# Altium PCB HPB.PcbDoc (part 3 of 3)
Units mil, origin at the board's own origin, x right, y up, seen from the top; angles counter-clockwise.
Board outline 7000 x 12000 mil, 6 copper layers (Top Layer, Int1 (GND), Int2 (Sign), Int3 (Sign), Int4 (PWR), Bottom Layer), stack 61.068 mil thick; 321 components, 232 nets, 1034 pads, 269 vias.
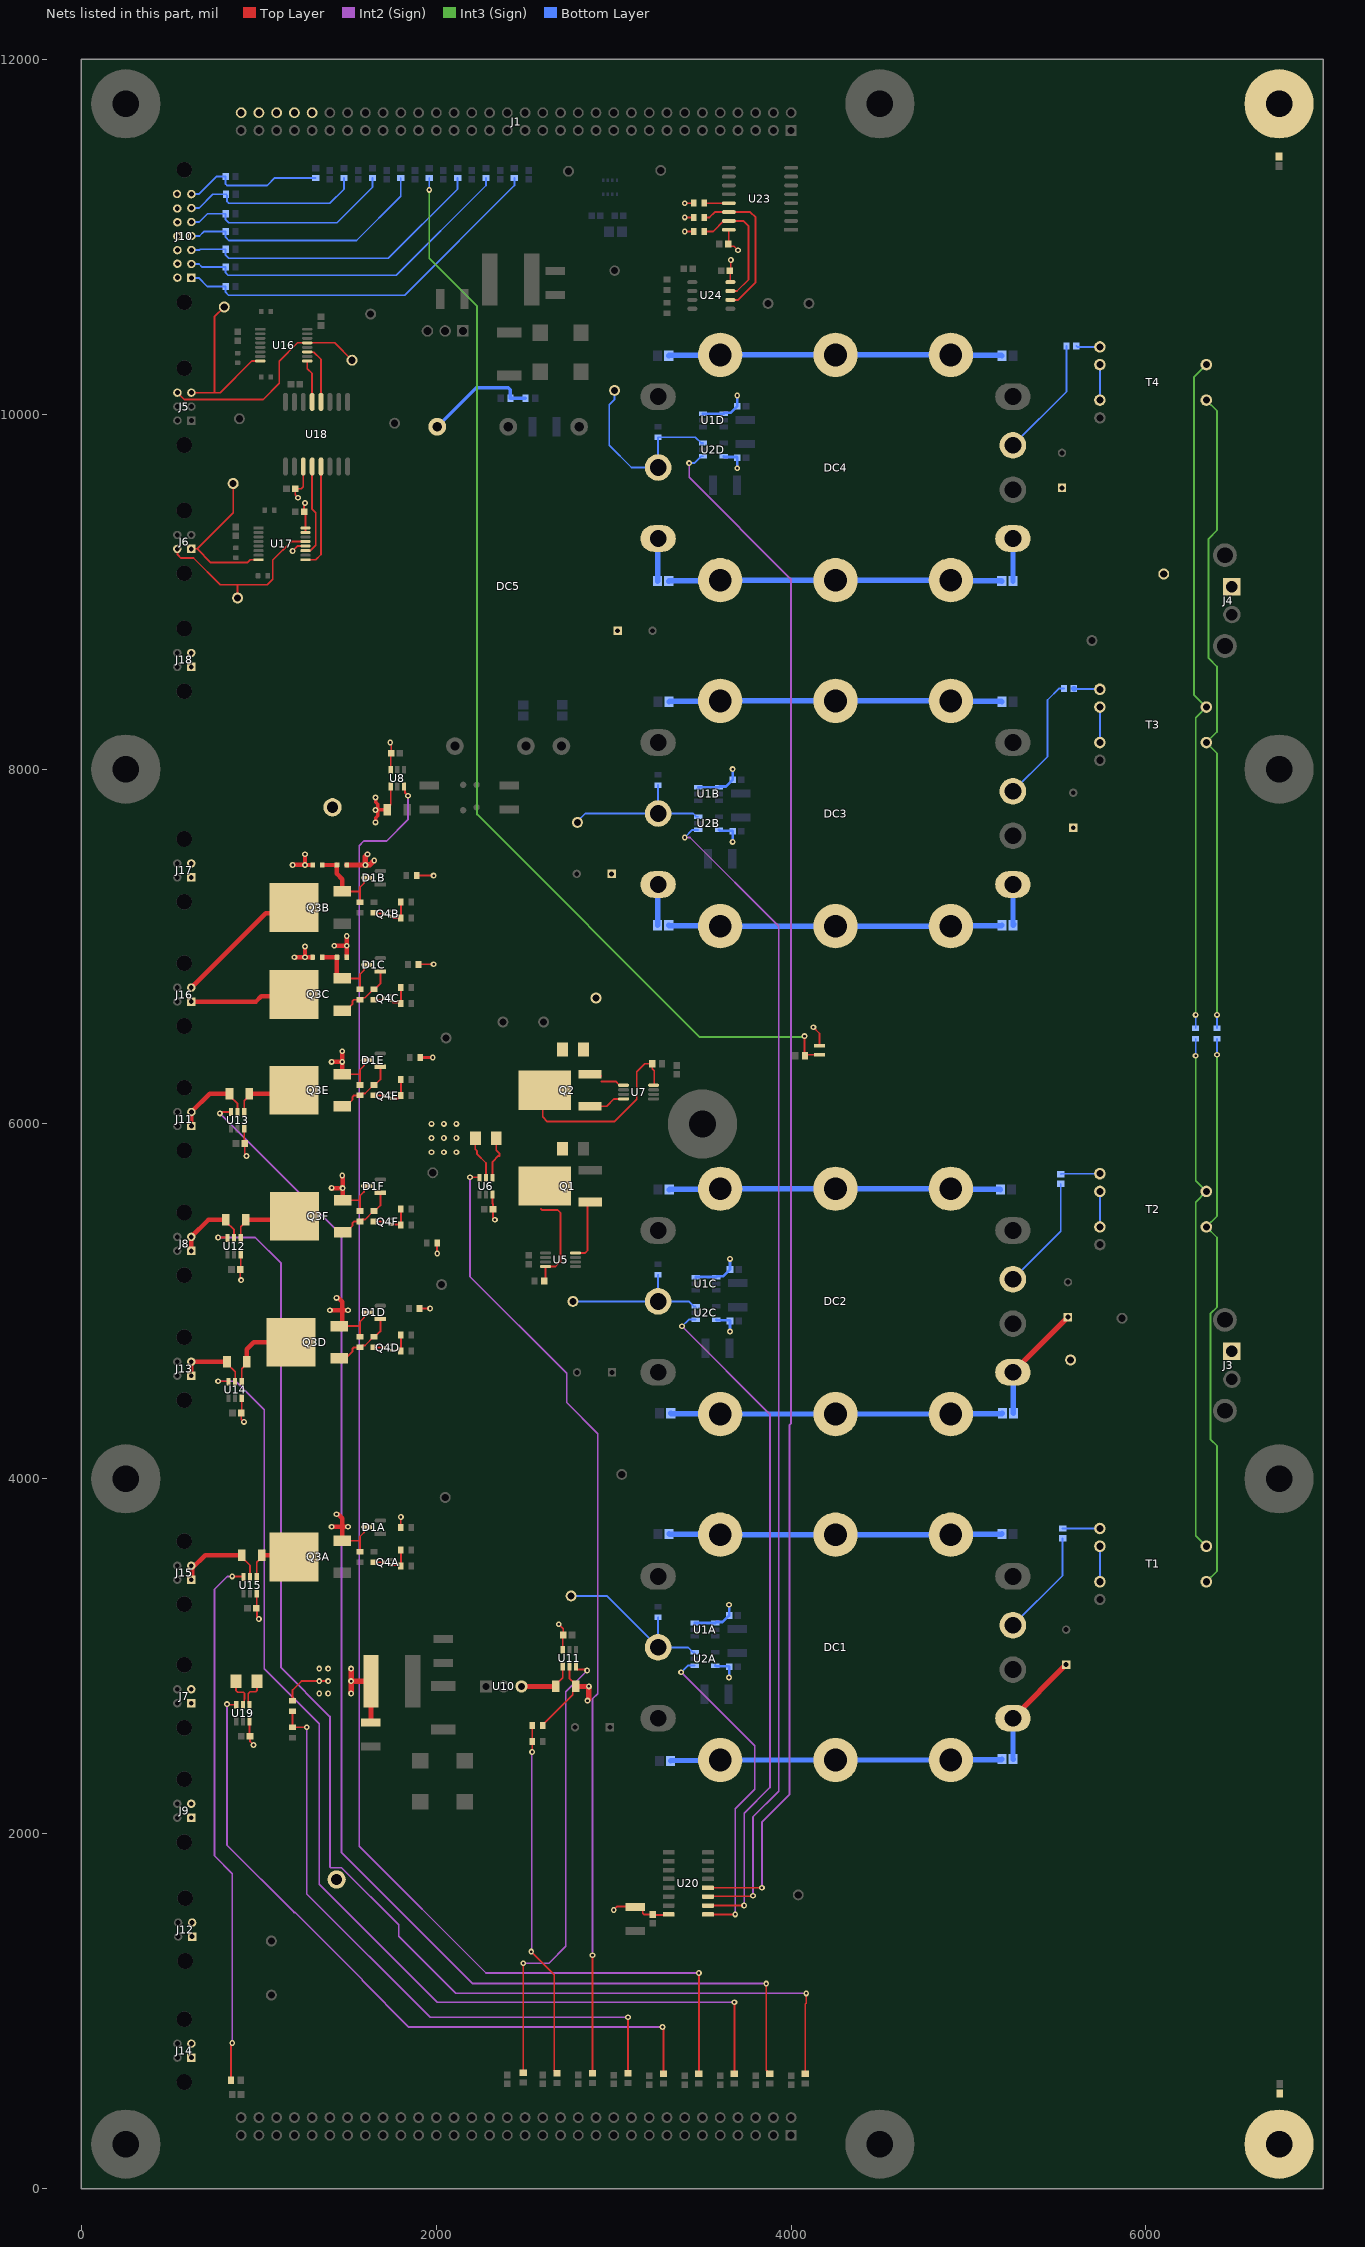
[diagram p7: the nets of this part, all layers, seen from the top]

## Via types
v1: diameter 33, hole 15, Top Layer to Bottom Layer, 269 vias

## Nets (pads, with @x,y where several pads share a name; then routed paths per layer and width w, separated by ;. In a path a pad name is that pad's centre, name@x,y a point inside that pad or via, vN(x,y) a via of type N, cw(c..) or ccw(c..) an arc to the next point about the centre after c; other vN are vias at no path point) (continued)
NetD1B_3: D1B.3 Q3B.3 R47.1 R48.1 R69B.1 | length 504.4
  Top Layer w10: Q3B.3@1470.12,7311.02 1568.22,7311.02 1570,7312.8 ; R69B.1@1570,7250 1570,7312.8 ; D1B.3@1608.19,7388.07 1598.8,7388.07 1592.47,7381.73 1592.47,7357.94 1570,7335.47 1570,7312.8
  Top Layer w25: R47.1@1357.56,7460 R48.1@1440,7460 1440,7410 1470.12,7379.88 Q3B.3@1470.12,7310.55
NetD1C_1: D1C.1 Q3C.1 R69C.2 R78C.2 | length 336.5
  Top Layer w10: Q3C.1@1489.8,6639.45 1528.24,6677.89 1528.24,6693.4 1535.31,6700.47 R69C.2@1570,6700.47 1580.75,6711.22 1597.76,6711.22 1646.06,6759.53 R78C.2@1650,6759.53 1653.94,6759.53 1685,6790.59 D1C.1@1685,6860.2
NetD1C_3: D1C.3 Q3C.3 R43.1 R44.1 R69C.1 | length 482
  Top Layer w10: Q3C.3@1470.12,6820.55 1568.22,6820.55 1570,6822.33 ; R69C.1@1570,6759.53 1570,6822.33 ; D1C.3@1608.19,6897.6 1598.8,6897.6 1592.47,6891.26 1592.47,6867.47 1570,6845 1570,6822.33
  Top Layer w25: R43.1@1357.56,6940 R44.1@1440,6940 1440,6837.58 1457.03,6820.55 Q3C.3@1470.12,6820.55
NetD1D_1: D1D.1 Q3D.1 R69D.2 R78D.2 | length 336.5
  Top Layer w10: Q3D.1@1489.8,4679.92 1528.24,4718.36 1528.24,4733.87 1535.31,4740.94 R69D.2@1570,4740.94 1580.75,4751.69 1597.76,4751.69 1646.06,4800 R78D.2@1650,4800 1653.94,4800 1685,4831.06 D1D.1@1685,4900.67
NetD1E_1: D1E.1 Q3E.1 R69E.2 R78E.2 | length 336.5
  Top Layer w10: Q3E.1@1489.8,6099.92 1528.24,6138.36 1528.24,6153.87 1535.31,6160.94 R69E.2@1570,6160.94 1580.75,6171.69 1597.76,6171.69 1646.06,6220 R78E.2@1650,6220 1653.94,6220 1685,6251.06 D1E.1@1685,6320.67
NetD1F_1: D1F.1 Q3F.1 R69F.2 R78F.2 | length 336.5
  Top Layer w10: Q3F.1@1489.8,5389.45 1528.24,5427.89 1528.24,5443.4 1535.31,5450.47 R69F.2@1570,5450.47 1580.75,5461.22 1597.76,5461.22 1646.06,5509.53 R78F.2@1650,5509.53 1653.94,5509.53 1685,5540.59 D1F.1@1685,5610.2
NetDC5_4: DC5.4 R27.1 R29.2 | length 642.9
  Bottom Layer w20: DC5.4@2005,9930 2225,10150 2405.84,10150 2417.56,10138.28 R29.2@2417.56,10090 ; R29.2@2417.56,10092.95 2420.51,10090 R27.1@2502.44,10090
NetFB1_2: FB1.2 MH6.1
NetFB2_2: FB2.2 MH3.1
NetJ5_3: J5.3 J38.1 U16.8 | length 967.9
  Top Layer w10: J5.3@619.37,10122.2 749.35,10122.2 ; J38.1@805,10605 749.35,10549.34 749.35,10122.2 ; U16.8@1007.57,10300.43 960.43,10300.43 782.2,10122.2 749.35,10122.2
NetJ5_6: J5.6 J36.1 U16.13 | length 1246.3
  Top Layer w10: J5.6@540.63,10122.2 579.25,10083.58 1023.58,10083.58 1115,10175 1115,10300 1217.8,10402.8 U16.13@1272.43,10402.8 1427.2,10402.8 J36.1@1525,10305
NetJ6_1: J6.1 J39.1 U17.8 | length 891.4
  Top Layer w10: J6.1@618.74,9241.26 635.81,9258.33 635.81,9244.19 637.36,9242.64 651.5,9242.64 ; J39.1@855,9610 855,9446.13 651.5,9242.64 ; U17.8@997.57,9180.43 950.43,9180.43 934.44,9164.44 729.7,9164.44 651.5,9242.64
NetJ6_3: J6.3 J37.1 U17.13 | length 1064.6
  Top Layer w10: J6.3@540,9241.26 541.5,9239.76 541.5,9208.5 560,9190 631.26,9190 781.26,9040 885,9040 ; J37.1@880,8965 880,9035 885,9040 ; U17.13@1262.43,9282.8 1182.8,9282.8 1078.65,9178.65 1078.65,9071.38 1047.27,9040 885,9040
NetJ7_1: J7.1 J7.2 J9.1 J9.2 J12.1 J12.2 J14.1 J14.2 R49.2 U19.5 | length 174.8
  Top Layer w10: R49.2@871.16,2860 871.16,2806.18 880.72,2796.62 912.8,2796.62 918.66,2790.76 918.66,2758.66 916.81,2756.81 916.81,2734.06 U19.5@910,2727.24
NetJ8_1: J8.1 J8.2 R37.1 U12.5 | length 435.6
  Top Layer w10: R37.1@813.9,5460 813.9,5449.17 860,5403.07 U12.5@860,5357.24
  Top Layer w25: J8.1@618.74,5285 J8.2@618.74,5363.74 714.37,5459.37 804.74,5459.37 805.37,5460 R37.1@813.9,5460
NetJ10_1: J10.1 R61.2 R66.2 | length 2178.7
  Bottom Layer w10: J10.1@619.38,10768.78 661.22,10768.78 710,10720 R66.2@812.44,10720 812.44,10687.56 828.7,10671.3 1821.3,10671.3 2440,11290 R61.2@2440,11332.44
NetJ10_2: J10.2 R62.2 R65.2 | length 1957.8
  Bottom Layer w10: J10.2@619.38,10847.52 662.48,10847.52 680,10830 R65.2@812.44,10830 812.44,10797.56 825.86,10784.14 1774.14,10784.14 2280,11290 R62.2@2280,11332.44
NetJ10_3: J10.3 R63.2 R64.2 | length 1765.9
  Bottom Layer w10: J10.3@619.38,10926.26 666.26,10926.26 670,10930 R64.2@812.44,10930 812.44,10897.56 830,10880 1730,10880 2120,11270 R63.2@2120,11332.44
NetJ10_4: J10.4 R52.2 R59.2 | length 1436.7
  Bottom Layer w10: J10.4@619.38,11005 665,11005 690,11030 R59.2@812.44,11030 812.44,10997.56 830,10980 1550,10980 1800,11230 R52.2@1800,11332.44
NetJ10_5: J10.5 R53.2 R58.2 | length 1214.8
  Bottom Layer w10: J10.5@619.38,11083.74 663.74,11083.74 710,11130 R58.2@812.44,11130 812.44,11097.56 830,11080 1440,11080 1640,11280 R53.2@1640,11332.44
NetJ10_6: J10.6 R54.2 R57.2 | length 1029.4
  Bottom Layer w10: J10.6@619.38,11162.48 662.48,11162.48 740,11240 R57.2@814.88,11240 820,11234.88 820,11200 830,11190 1400,11190 1480,11270 R54.2@1480,11332.44
NetJ10_7: J10.7 R55.2 R56.2 | length 804.7
  Bottom Layer w10: J10.7@619.38,11241.22 661.22,11241.22 760,11340 R56.2@812.44,11340 812.44,11297.56 820,11290 1045.94,11290 1088.39,11332.44 R55.2@1320,11332.44
NetJ11_1: J11.1 J11.2 R39.1 U13.5 | length 458.6
  Top Layer w10: R39.1@833.9,6170 833.9,6159.17 880,6113.07 U13.5@880,6067.24
  Top Layer w25: J11.1@619.37,5988.46 J11.2@619.37,6067.2 723.27,6171.1 824.74,6171.1 825.85,6170 R39.1@833.9,6170
NetJ13_1: J13.1 J13.2 R41.1 U14.5 | length 401.4
  Top Layer w10: R41.1@820,4650 866.1,4603.9 U14.5@866.1,4548.07
  Top Layer w25: J13.1@618.74,4581.26 J13.2@618.74,4660 819.17,4660 R41.1@820,4660.83
NetJ15_1: J15.1 J15.2 R45.1 U15.5 | length 524
  Top Layer w10: R45.1@903.9,3559.17 950,3513.07 U15.5@950,3447.24
  Top Layer w25: J15.1@618.74,3431.26 624.86,3437.38 J15.2@624.86,3497.38 ; J15.2@618.74,3510 618.74,3503.5 J15.2@624.86,3497.38 ; R45.1@903.9,3570 697.48,3570 J15.2@624.86,3497.38
NetJ16_1: J16.1 Q3C.4 | length 596.3
  Top Layer w25: J16.1@618.74,6690 983.7,6690 1013.7,6720 1188.46,6720 Q3C.4@1198.46,6730
NetJ16_2: J16.2 Q3B.4 | length 766.6
  Top Layer w25: J16.2@618.74,6768.74 1037.81,7187.81 1166.28,7187.81 Q3B.4@1198.46,7220
NetQ1_1: Q1.1 U5.4 | length 346.2
  Top Layer w10: U5.4@2784.65,5273.39 2838.39,5273.39 2851.97,5286.97 Q1.1@2851.97,5560.24
NetQ1_2: Q1.2 Q2.2 R15.2 R18.2 R19.1 R75.2 R76.1 U5.8 U6.4 U7.8 | length 1985.2
  Top Layer w10: U6.4@2317.4,5697.24 2317.4,5787.4 2350,5820 2355.58,5820 2355.58,5834.42 2337.68,5852.32 R19.1@2337.68,5920 R19.1@2350.07,5907.61 ; 2590,5520.86 2595.86,5515 2684.82,5515 2700,5499.82 2700,5225 2671.61,5196.61 U5.8@2615.35,5196.61 2615.35,5120.35 R75.2@2610,5115 ; Q1.2@2590,5640 Q1.2@2600,5650 ; Q2.2@2599.45,6190 2599.45,6040.55 2626.2,6013.8 3003.8,6013.8 3130,6140 3130,6295 3175,6340 3215.47,6340 3216.92,6338.55 3216.92,6311.17 3227.78,6300.31 3227.78,6221.52 U7.8@3224.65,6218.39
NetQ2_1: Q2.1 U7.4 | length 221.1
  Top Layer w10: Q2.1@2851.42,6100.24 2960.24,6100.24 3001.61,6141.61 U7.4@3055.35,6141.61
NetQ3A_4: Q3A.4 R45.2 U15.4 | length 326.6
  Top Layer w10: U15.4@987.4,3447.24 987.4,3530.47 1016.1,3559.17 R45.2@1016.1,3570
  Top Layer w25: R45.2@1016.1,3559.17 1016.1,3560.85 1025.26,3570 1188.46,3570 Q3A.4@1198.46,3560
NetQ3D_4: Q3D.4 R41.2 U14.4 | length 458.7
  Top Layer w10: U14.4@903.5,4548.07 903.5,4621.3 932.2,4650 R41.2@932.2,4660.83
  Top Layer w25: R41.2@932.2,4660.83 932.2,4730.81 971.4,4770 Q3D.4@1180,4770
NetQ3E_4: Q3E.4 R39.2 U13.4 | length 375.3
  Top Layer w10: U13.4@917.4,6067.24 917.4,6130.47 946.1,6159.17 R39.2@946.1,6170
  Top Layer w25: R39.2@946.1,6170 1178.46,6170 Q3E.4@1198.46,6190
NetQ3F_4: Q3F.4 R37.2 U12.4 | length 396.8
  Top Layer w10: U12.4@897.4,5357.24 897.4,5420.47 926.1,5449.17 R37.2@926.1,5460
  Top Layer w25: R37.2@926.1,5460 1180,5460 Q3F.4@1200,5480
NetQ4A_1: Q4A.1 R70A.2 R71A.2 | length 144.6
  Top Layer w10: Q4A.1@1747.64,3514.25 1796.22,3514.25 R71A.2@1800.47,3510 R70A.2@1800.47,3600
NetQ4A_3: Q4A.3 R78A.1 | length 52.6
  Top Layer w10: R78A.1@1650,3530.47 1650.47,3530 Q4A.3@1702.36,3530
NetQ4B_1: Q4B.1 R70B.2 R71B.2 | length 153
  Top Layer w10: Q4B.1@1747.64,7170 1748.62,7170 1758.62,7160 R71B.2@1800.47,7160 ; R71B.2@1796.22,7174.72 1800.47,7170.47 R70B.2@1800.47,7250 R70B.2@1800.47,7260.47
NetQ4B_3: Q4B.3 R78B.1 | length 55.2
  Top Layer w10: R78B.1@1650.47,7190.47 R78B.1@1650,7190.94 1655.2,7185.75 Q4B.3@1702.36,7185.75
NetQ4C_1: Q4C.1 R70C.2 R71C.2 | length 148.7
  Top Layer w10: Q4C.1@1747.64,6694.25 1757.64,6684.25 1796.22,6684.25 R71C.2@1800.47,6680 R70C.2@1800.47,6770
NetQ4C_3: Q4C.3 R78C.1 | length 56.7
  Top Layer w10: R78C.1@1650,6700.47 1650.47,6700 1692.36,6700 Q4C.3@1702.36,6710
NetQ4D_1: Q4D.1 R70D.2 R71D.2 | length 144.6
  Top Layer w10: Q4D.1@1747.64,4724.72 1796.22,4724.72 1800.47,4720.47 R70D.2@1800.47,4810.47
NetQ4D_3: Q4D.3 R78D.1 | length 52.6
  Top Layer w10: R78D.1@1650,4740.94 1650.47,4740.47 Q4D.3@1702.36,4740.47
NetQ4E_1: Q4E.1 R70E.2 R71E.2 | length 151.7
  Top Layer w10: Q4E.1@1747.64,6144.25 1788.66,6144.25 1800.47,6156.06 R71E.2@1800.47,6160 R70E.2@1800.47,6250
NetQ4E_3: Q4E.3 R78E.1 | length 52.6
  Top Layer w10: R78E.1@1650,6160.94 1650.47,6160.47 Q4E.3@1702.36,6160.47
NetQ4F_1: Q4F.1 R70F.2 R71F.2 | length 144.6
  Top Layer w10: Q4F.1@1747.64,5434.25 1796.22,5434.25 R71F.2@1800.47,5430 R70F.2@1800.47,5520
NetQ4F_3: Q4F.3 R78F.1 | length 52.6
  Top Layer w10: R78F.1@1650,5450.47 1650.47,5450 Q4F.3@1702.36,5450
NetR1_1: R1.1 T1.4 | length 210
  Bottom Layer w10: R1.1@5530,3720 T1.4@5740,3720
NetR6_1: R6.1 T2.4 | length 221
  Bottom Layer w10: R6.1@5520,5717.56 5522.44,5720 T2.4@5740,5720
NetR12_1: R12.1 T1.6 T2.6 | length 3165.3
  Int3 (Sign) w10: T1.6@6340,3420 6400,3480 6400,4186.34 6362.83,4223.5 6362.83,4929.84 6400,4967.01 6400,5360 T2.6@6340,5420 6400,5480 v1(6400,6390)
  Bottom Layer w10: v1(6400,6390) R12.1@6400,6480
NetR12_2: R12.2 T3.6 T4.6 | length 3654.6
  Int3 (Sign) w10: T4.6@6340,10080 6400,10020 6400,9346.16 6352.83,9299 6352.83,8625.16 6400,8577.99 6400,8210 T3.6@6340,8150 6400,8090 v1(6400,6615)
  Bottom Layer w10: R12.2@6400,6539.06 v1(6400,6615)
NetR13_1: R13.1 T1.5 T2.5 | length 2934.6
  Int3 (Sign) w10: v1(6280,6385) 6280,5680 T2.5@6340,5620 6280,5560 6280,3680 T1.5@6340,3620
  Bottom Layer w10: v1(6280,6385) R13.1@6280,6480
NetR13_2: R13.2 T3.5 T4.5 | length 3823.8
  Int3 (Sign) w10: v1(6280,6615) 6280,8290 T3.5@6340,8350 6270,8420 6270,10210 T4.5@6340,10280
  Bottom Layer w10: R13.2@6280,6539.06 v1(6280,6615)
NetR14_1: R14.1 T3.4 | length 149.5
  Bottom Layer w10: R14.1@5595.06,8452.5 T3.4@5737.5,8452.5
  Bottom Layer w30: R14.1@5592.56,8455 R14.1@5595.06,8452.5 ; T3.4@5737.5,8452.5 T3.4@5740,8450
NetR17_1: R17.1 T4.4 | length 134.5
  Bottom Layer w10: R17.1@5607.56,10385 5612.56,10380 T4.4@5740,10380
NetR20_1: R20.1 R23.1 R24.2 | length 3524
  Top Layer w10: R20.1@1190,2690.47 R24.2@1190,2599.53 1269.53,2599.53 v1(1270,2600) ; R23.1@3080,650 v1(3080,965)
  Int2 (Sign) w10: v1(1270,2600) 1270,1660 1965,965 v1(3080,965)
NetR22_1: R22.1 U6.6 | length 5414.8
  Top Layer w10: v1(2190,5700) 2239.84,5700 U6.6@2242.6,5697.24 ; R22.1@2880,649.56 v1(2880,1315)
  Int2 (Sign) w10: v1(2190,5700) 2190,5140 2735,4595 2735,4430 2910,4255 2910,2789.53 2880,2759.53 v1(2880,1315)
NetR28_1: R28.1 U8.6 | length 8950.3
  Top Layer w10: U8.6@1817.4,7902.76 1823.9,7896.26 1823.9,7866.1 v1(1840,7850) ; R28.1@3480,647.56 v1(3480,1215)
  Int2 (Sign) w10: v1(1840,7850) 1840,7715 1720,7595 1590.86,7595 1565,7569.14 1565,1930 2280,1215 v1(3480,1215)
NetR31_2: R31.2 U10.3 U11.4 | length 322.7
  Top Layer w10: R31.2@2673.9,2830 2673.9,2840.83 2712.6,2879.53 U11.4@2712.6,2942.76
  Top Layer w30: U10.3@2480,2830 R31.2@2673.9,2830
NetR33_1: R33.1 R35.1 R36.2 | length 2023.9
  Top Layer w10: v1(2535,1335) 2664.33,1205.67 2664.33,662.83 2677.05,650.12 R35.1@2680,650.12 ; v1(2540,2460) 2540.47,2460.47 R36.2@2540.47,2520 R33.1@2540.47,2610
  Int2 (Sign) w10: v1(2535,1335) 2537.5,1337.5 2537.5,2457.5 v1(2540,2460)
NetR34_1: R34.1 U11.6 | length 2579.3
  Top Layer w10: R34.1@2490,652.56 v1(2490,1270) ; U11.6@2787.4,2942.76 2787.4,2932.91 2794.21,2926.1 2839.84,2926.1 2845.94,2920 v1(2850,2920)
  Int2 (Sign) w10: v1(2490,1270) 2635,1270 2730,1365 2730,2800 v1(2850,2920)
NetR38_1: R38.1 U12.6 | length 7456.4
  Top Layer w10: v1(770,5360) 819.84,5360 U12.6@822.6,5357.24 ; R38.1@4080,647.56 4080,1040 4085,1045 v1(4085,1100)
  Int2 (Sign) w10: v1(770,5360) 980,5360 1125,5215 1125,2935 1400,2660 1400,1814.08 1405.86,1808.22 1465.71,1808.22 1787.85,1486.08 1787.85,1422.15 2110,1100 v1(4085,1100)
NetR40_1: R40.1 U13.6 | length 7733.3
  Top Layer w10: v1(780,6060) 787.24,6067.24 U13.6@842.6,6067.24 ; v1(3860,1155) 3860,667.56 3864.33,663.23 3864.33,660.28 3877.05,647.56 R40.1@3880,647.56
  Int2 (Sign) w10: v1(780,6060) 1465,5375 1465,1895 2205,1155 v1(3860,1155)
NetR42_1: R42.1 U14.6 | length 6207.1
  Top Layer w10: v1(770,4550) 826.77,4550 U14.6@828.7,4548.07 ; R42.1@3680,647.56 v1(3680,1050)
  Int2 (Sign) w10: v1(770,4550) 870,4550 1030,4390 1030,2930 1340,2620 1340,1715 2005,1050 v1(3680,1050)
NetR46_1: R46.1 U15.6 | length 3005.7
  Top Layer w10: R46.1@842.44,610 842.44,812.44 v1(850,820) ; v1(850,3450) 909.84,3450 U15.6@912.6,3447.24
  Int2 (Sign) w10: v1(850,820) 850,1775 750,1875 750,3377.24 822.5,3449.74 849.74,3449.74 v1(850,3450)
NetR50_1: R50.1 U19.6 | length 3995.7
  Top Layer w10: v1(820,2730) 822.76,2727.24 U19.6@872.6,2727.24 ; v1(3275,910) 3275,905.94 3280,900.94 R50.1@3280,647.56
  Int2 (Sign) w10: v1(820,2730) 820,1935 1198.54,1556.46 1203.46,1556.46 1582.01,1177.91 1582.01,1172.99 1845,910 v1(3275,910)
NetR51_2: R51.2 R60.2 U21.2 | length 6261.8
  Top Layer w10: v1(4075,6495) 4075,6387.56 R60.2@4077.56,6385 4082.56,6390 U21.2@4160,6390
  Int3 (Sign) w10: v1(1960,11265) 1960,10880 2230,10610 2230,7745 3485,6490 4070,6490 v1(4075,6495)
  Bottom Layer w10: v1(1960,11265) R51.2@1960,11332.44
NetR72_1: R72.1 U23.14 U24.6 | length 864.7
  Top Layer w10: R72.1@3509.53,11110 3540,11110 3570,11140 U23.14@3648.39,11140 3770,11140 3799.65,11110.35 3799.65,10743.82 3700.83,10645 U24.6@3657.28,10645
NetR73_1: R73.1 U23.15 U24.7 | length 717.4
  Top Layer w10: R73.1@3509.53,11030 3559.63,11030 3619.63,11090 U23.15@3648.39,11090 3730,11090 3760,11060 3760,10760.03 3694.97,10695 U24.7@3657.28,10695
NetR74_1: R74.1 U23.13 | length 138.9
  Top Layer w10: R74.1@3509.53,11190 U23.13@3648.39,11190
NetT1_2: T1.2 T1.3 | length 200
  Bottom Layer w10: T1.2@5740,3420 T1.3@5740,3620
NetT2_2: T2.2 T2.3 | length 200
  Bottom Layer w10: T2.2@5740,5420 T2.3@5740,5620
NetT3_2: T3.2 T3.3 | length 200
  Bottom Layer w10: T3.2@5740,8150 T3.3@5740,8350
NetT4_2: T4.2 T4.3 | length 200
  Bottom Layer w10: T4.2@5740,10080 T4.3@5740,10280
NetU16_9: U16.9 U18.13 | length 241.9
  Top Layer w10: U16.9@1272.43,10300.43 1272.43,10257.57 1300,10230 U18.13@1300,10070
NetU16_11: U16.11 U18.12 | length 334.8
  Top Layer w10: U16.11@1272.43,10351.61 1273.67,10350.38 1309.62,10350.38 1350,10310 U18.12@1350,10070
NetU17_9: U17.9 U18.5 | length 595.6
  Top Layer w10: U17.9@1262.43,9180.43 1320.43,9180.43 1350,9210 U18.5@1350,9705.83
NetU17_11: U17.11 U18.4 | length 522.9
  Top Layer w10: U17.11@1262.43,9231.61 1263.67,9232.85 1291.88,9232.85 1320,9260.97 1320,9445.16 1300,9465.16 U18.4@1300,9705.83
OUTA: U2A.1 U20.1 | length 1828.7
  Top Layer w10: U20.1@3531.22,1545 v1(3685,1545)
  Int2 (Sign) w10: v1(3380,2910) 3795,2495 3795,2250 3685,2140 v1(3685,1545)
  Bottom Layer w10: v1(3380,2910) 3417.6,2947.6 U2A.1@3456.93,2947.6
OUTB: U2B.1 U20.3 | length 6612.6
  Top Layer w10: U20.3@3531.22,1645 3533.72,1647.5 3782.5,1647.5 v1(3785,1650)
  Int2 (Sign) w10: v1(3400,7615) 3430,7615 3930,7115 3930,2240 3785,2095 v1(3785,1650)
  Bottom Layer w10: v1(3400,7615) 3442.6,7657.6 U2B.1@3476.93,7657.6
OUTC: U2C.1 U20.2 | length 3826.4
  Top Layer w10: U20.2@3531.22,1595 v1(3735,1595)
  Int2 (Sign) w10: v1(3385,4860) 3880,4365 3880,2260 3735,2115 v1(3735,1595)
  Bottom Layer w10: v1(3385,4860) 3422.6,4897.6 U2C.1@3461.93,4897.6
OUTD: U2D.1 U20.4 | length 8733.1
  Top Layer w10: U20.4@3531.22,1695 v1(3835,1695)
  Int2 (Sign) w10: v1(3425,9725) 3425,9645 3998.5,9071.5 3998.5,4311.62 3990,4303.12 3990,2220 3835,2065 v1(3835,1695)
  Bottom Layer w10: v1(3425,9725) 3453.66,9725 3492.26,9763.6 U2D.1@3503.09,9763.6
P187_L: C1.1 C3.1 C7.1 C14.1 DC1.1 DC2.1 J3.A J19.1 | length 1329.3
  Top Layer w30: DC1.1@5250,2650 5250,2653.15 C3.1@5550,2953.15 ; DC2.1@5250,4600 5250,4601.57 C14.1@5560,4911.57
  Bottom Layer w30: DC1.1@5250,2650 5250.75,2649.25 5250.75,2420.75 C1.1@5251.5,2420 ; DC2.1@5250,4600 5251.5,4598.5 5251.5,4371.5 C7.1@5252.99,4370
P187_R: C18.1 C20.1 C26.1 C28.1 DC3.1 DC4.1 J4.A J21.1 | length 479.2
  Bottom Layer w30: DC3.1@5250,7350 5250.75,7349.25 5250.75,7120.75 C18.1@5251.5,7120 5256.5,7125 C18.1@5256.5,7126.5 ; C26.1@5250,9060 DC4.1@5250,9300
R_24V: C19.2 C21.1 C27.2 C29.1 DC3.7 DC4.7 J26.1 Q2.3 R18.1 U7.1 | length 689.8
  Top Layer w10: Q2.3@2851.42,6279.76 2856.18,6275 2924.14,6275 Q2.3@2930,6269.14 ; 2930,6240 3011.1,6240 3032.72,6218.39 U7.1@3055.35,6218.39
  Bottom Layer w30: C19.2@3247.01,7120 3248.5,7121.5 3248.5,7348.5 DC3.7@3250,7350 ; C27.2@3247.01,9060 3248.5,9061.5 3248.5,9298.5 DC4.7@3250,9300
SYS_24V: C43.2 D1A.3 D1D.3 D1E.3 D1F.3 J1.56 J1.58 J1.60 J1.62 J1.64 L3.1 Q3A.3 Q3D.3 Q3E.3 Q3F.3 R19.2 R20.2 R26.2 R44.2 R48.2 R49.1 R69A.1 R69D.1 R69E.1 R69F.1 TP1.1 U6.5 U8.4 U19.4 | length 3931.7
  Top Layer w10: U19.4@947.4,2727.24 940.59,2734.06 940.59,2749.17 940,2749.76 940,2760 939.41,2760.59 939.41,2789.41 950,2800 982.98,2800 988.84,2805.86 R49.1@988.84,2860 ; R20.2@1190,2749.53 1190,2810 1240,2860 v1(1390,2860) ; Q3A.3@1470.12,3650.55 1568.22,3650.55 1570,3652.33 ; Q3D.3@1470.12,4861.02 1568.22,4861.02 1570,4862.8 ; Q3F.3@1470.12,5570.55 1568.22,5570.55 1570,5572.33 ; Q3E.3@1470.12,6281.02 1568.22,6281.02 1570,6282.8 ; R69A.1@1570,3589.53 1570,3652.33 ; R69D.1@1570,4800 1570,4862.8 ; R69F.1@1570,5509.53 1570,5572.33 ; R69E.1@1570,6220 1570,6282.8 ; D1A.3@1608.19,3727.6 1598.8,3727.6 1592.47,3721.26 1592.47,3697.47 1570,3675 1570,3652.33 ; D1D.3@1608.19,4938.07 1598.8,4938.07 1592.47,4931.73 1592.47,4907.94 1570,4885.47 1570,4862.8 ; D1F.3@1608.19,5647.6 1598.8,5647.6 1592.47,5641.26 1592.47,5617.47 1570,5595 1570,5572.33 ; D1E.3@1608.19,6358.07 1598.8,6358.07 1592.47,6351.73 1592.47,6327.94 1570,6305.47 1570,6282.8 ; R26.2@1723.9,7770 1723.9,7780.83 1742.6,7799.53 U8.4@1742.6,7902.76 ; R19.2@2220,5920 2220,5858 2230,5848 2230,5830 2280,5780 U6.5@2280,5697.24
  Top Layer w20: v1(1657.5,7700) 1658.46,7700.96 1658.46,7725.96 1670,7737.5 v1@1670,7770 ; v1(1657.5,7770) v1@1670,7770 ; v1(1657.5,7840) 1658.46,7839.04 1658.46,7814.04 1670,7802.5 v1@1670,7770 ; R26.2@1723.9,7770 v1@1670,7770
  Top Layer w25: v1(1400,4950) 1470,4950 ; v1(1410,3730) 1470,3730 ; v1(1410,5640) 1411.65,5638.35 v1(1471.65,5638.35) ; v1(1410,6350) v1(1470,6350) ; v1(1425,7005) v1(1495,7005) ; v1(1437.5,3800) 1447.5,3800 1470,3777.5 1470,3730 ; v1(1437.5,5020) 1447.5,5020 1470,4997.5 1470,4950 ; v1(1470,5710) 1471.65,5708.35 v1(1471.65,5638.35) ; v1(1470,6410) v1(1470,6350) ; Q3A.3@1470.12,3650.55 1470.12,3729.88 ; Q3D.3@1470.12,4870.55 1470,4870.67 1470,4950 ; Q3E.3@1470.12,6280.55 1470.12,6349.88 v1(1470,6350) ; Q3F.3@1471.65,5570.55 v1(1471.65,5638.35) ; v1(1495,7060) v1(1495,7005) ; R44.2@1495.12,6940 1495.12,7004.88 v1(1495,7005) ; v1(1502.5,3730) 1502.38,3729.88 1470.12,3729.88 ; v1(1502.5,4950) 1470,4950 ; 1470,3730 1470.12,3729.88
  Top Layer w30: R48.2@1495.12,7460 v1(1600,7460) ; v1(1520,2790) v1(1520,2860) ; v1(1520,2930) v1(1520,2860) ; v1(1612.5,7520) 1600,7507.5 v1(1600,7460) ; C43.2@1630,2627.91 1631.89,2629.8 L3.1@1631.89,2860 v1(1520,2860) ; v1(1650,7485) 1649.19,7485 1624.76,7460.57 1600.57,7460.57 v1(1600,7460)
  other v1: 1340,2790 1390,2790 1340,2860 1340,2930 1390,2930 1972.75,5840.93 2042.75,5840.93 2112.75,5840.93 1972.75,5920.93 2042.75,5920.93 2112.75,5920.93 1972.75,6000.93 2042.75,6000.93 2112.75,6000.93
V1_L_MT1: C1.2 C2.1 DC1.MT4 DC1.MT5 DC1.MT6 | length 1872.6
  Bottom Layer w30: C2.1@3320,2410 3322.5,2412.5 3597.5,2412.5 DC1.MT4@3600,2415 DC1.MT5@4250,2415 DC1.MT6@4900,2415 4902.5,2417.5 5186,2417.5 C1.2@5188.5,2420
V1_L_MT2: C5.2 C6.1 DC1.MT1 DC1.MT2 DC1.MT3 | length 1881.2
  Bottom Layer w30: C6.1@3311.5,3690 3314,3687.5 3597.5,3687.5 DC1.MT3@3600,3685 DC1.MT2@4250,3685 DC1.MT1@4900,3685 4902.5,3687.5 5186,3687.5 C5.2@5188.5,3690
V1_L_PR: DC1.3 R1.2 | length 605.9
  Bottom Layer w10: DC1.3@5250,3175 5530,3455 R1.2@5530,3664.88
V1_L_S: DC1.6 J24.1 R11.1 U2A.3 | length 999
  Bottom Layer w10: J24.1@2760,3340 2960,3340 DC1.6@3250,3050 ; R11.1@3250,3220.47 DC1.6@3250,3050 ; U2A.3@3456.93,3022.4 3446.1,3022.4 3418.5,3050 DC1.6@3250,3050
V1_R_MT1: C18.2 C19.1 DC3.MT4 DC3.MT5 DC3.MT6 | length 1882.6
  Bottom Layer w30: C19.1@3310,7120 3312.5,7117.5 3597.5,7117.5 DC3.MT4@3600,7115 DC3.MT5@4250,7115 DC3.MT6@4900,7115 4902.5,7117.5 5186,7117.5 C18.2@5188.5,7120
V1_R_MT2: C22.2 C23.1 DC3.MT1 DC3.MT2 DC3.MT3 | length 1881.2
  Bottom Layer w30: C23.1@3311.5,8380 3314,8382.5 3597.5,8382.5 DC3.MT3@3600,8385 DC3.MT2@4250,8385 DC3.MT1@4900,8385 4902.5,8382.5 5186,8382.5 C22.2@5188.5,8380
V1_R_PR: DC3.3 R14.2 | length 715.1
  Bottom Layer w10: DC3.3@5250,7875 5445,8070 5445,8390 5510,8455 R14.2@5537.44,8455
V1_R_S: DC3.6 J27.1 R21.1 U2B.3 | length 873.6
  Bottom Layer w10: J27.1@2795,7700 2795,7705.48 2839.52,7750 DC3.6@3250,7750 ; R21.1@3250,7910.47 DC3.6@3250,7750 ; U2B.3@3476.93,7732.4 3466.1,7732.4 3448.5,7750 DC3.6@3250,7750
V2_L_MT1: C7.2 C8.1 DC2.MT4 DC2.MT5 DC2.MT6 | length 1872.6
  Bottom Layer w30: C8.1@3321.5,4370 3324,4367.5 3597.5,4367.5 DC2.MT4@3600,4365 DC2.MT5@4250,4365 DC2.MT6@4900,4365 4902.5,4367.5 5187.5,4367.5 C7.2@5190,4370
V2_L_MT2: C16.2 C17.1 DC2.MT1 DC2.MT2 DC2.MT3 | length 1871.2
  Bottom Layer w30: C17.1@3312.99,5630 3315.49,5632.5 3597.5,5632.5 DC2.MT3@3600,5635 DC2.MT2@4250,5635 DC2.MT1@4900,5635 4902.5,5632.5 5177.5,5632.5 C16.2@5180,5630
V2_L_PR: DC2.3 R6.2 | length 649.3
  Bottom Layer w10: DC2.3@5250,5125 5520,5395 R6.2@5520,5662.44
V2_L_S: DC2.6 J25.1 R16.1 U2C.3 | length 853.8
  Bottom Layer w10: J25.1@2770,5000 DC2.6@3250,5000 ; R16.1@3250,5150.47 DC2.6@3250,5000 ; U2C.3@3461.93,4972.4 3451.1,4972.4 3423.5,5000 DC2.6@3250,5000
V2_R_MT1: C26.2 C27.1 DC4.MT4 DC4.MT5 DC4.MT6 | length 1881.2
  Bottom Layer w30: C27.1@3310,9060 3312.5,9062.5 3597.5,9062.5 DC4.MT4@3600,9065 DC4.MT5@4250,9065 DC4.MT6@4900,9065 4902.5,9062.5 5184.51,9062.5 C26.2@5187.01,9060
V2_R_MT2: C30.2 C31.1 DC4.MT1 DC4.MT2 DC4.MT3 | length 1882.6
  Bottom Layer w30: C31.1@3310,10330 3312.5,10332.5 3597.5,10332.5 DC4.MT3@3600,10335 DC4.MT2@4250,10335 DC4.MT1@4900,10335 4902.5,10332.5 5186,10332.5 C30.2@5188.5,10330
V2_R_PR: DC4.3 R17.2 | length 684.4
  Bottom Layer w10: DC4.3@5250,9825 5551.79,10126.79 R17.2@5551.79,10384.35
V2_R_S: DC4.6 J28.1 R25.1 U2D.3 | length 1086
  Bottom Layer w10: J28.1@3005,10135 3005,10084.13 2975,10054.13 2975,9825 3100,9700 DC4.6@3250,9700 R25.1@3250,9870.47 3460.19,9870.47 3492.26,9838.4 U2D.3@3503.09,9838.4
VCCA: C13.2 C38.2 C49.2 C52.2 C53.2 C54.2 C65.2 C66.2 C70.2 C71.2 C72.2 C85.2 C86.2 C87.2 C90A.2 C90B.2 C90C.2 C90D.2 C93A.2 C93B.2 C93C.2 C93D.2 J10.8 J10.9 J10.10 J10.11 J10.12 J10.13 J10.14 J17.1 J17.2 J18.1 J18.2 R31.1 R33.2 R43.2 R47.2 R72.2 R73.2 R74.2 R77A.2 R77B.2 R77C.2 R77D.2 R77E.2 R77F.2 TP2.1 U1A.3 U1A.4 U1B.3 U1B.4 U1C.3 U1C.4 U1D.3 U1D.4 U2A.5 U2B.5 U2C.5 U2D.5 U6.3 U8.3 U11.3 U11.5 U12.3 U13.3 U14.3 U15.3 U17.12 U17.15 U17.16 U18.3 U19.3 U20.16 U21.1 U23.16 U24.8 | length 5544.5
  Top Layer w10: U12.3@897.4,5262.76 897.4,5182.8 C53.2@894.61,5180 894.61,5129.45 900,5124.06 v1(900,5120) ; U14.3@903.5,4453.58 903.5,4373.62 C52.2@900.71,4370.83 900.71,4336.22 v1(916.1,4320.83) ; U13.3@917.4,5972.76 917.4,5892.6 C54.2@920,5890 920,5834.06 930,5824.06 v1(930,5820) ; U19.3@947.4,2632.76 947.4,2552.6 C70.2@950,2550 950,2520 v1(970,2500) ; U15.3@987.4,3352.76 987.4,3272.8 C87.2@984.61,3270 990,3264.61 990,3220 v1(1000,3210) ; v1(1190,9230) 1217.2,9257.2 U17.12@1262.43,9257.2 ; v1(1220,9530) 1220,9530.91 1204.61,9546.3 C66.2@1204.61,9580 1238.31,9580 1250,9591.69 U18.3@1250,9705.83 ; v1(1260,9500) 1254.61,9494.61 C65.2@1254.61,9450 1262.43,9442.18 U17.16@1262.43,9359.57 U17.15@1262.43,9333.98 ; v1(1740,8150) 1745.39,8144.61 C38.2@1745.39,8090 1742.6,8087.2 U8.3@1742.6,7997.24 ; R77A.2@1800,3725 v1(1800,3785) ; R77B.2@1890,7400 v1(1985,7400) ; R77C.2@1899.53,6900 v1(1985,6900) ; R77D.2@1905,4960 v1(1965,4960) ; R77F.2@2004.53,5330 2004.53,5270.47 v1(2005,5270) ; U6.3@2317.4,5602.76 2317.4,5552.6 2319.21,5550.79 C13.2@2319.21,5520 2319.21,5470.79 v1(2330,5460) ; R33.2@2599.53,2610 2599.53,2613.94 2769.45,2783.86 2769.45,2813.35 R31.1@2786.1,2830 2786.1,2840.83 2750,2876.93 U11.5@2750,2942.76 ; v1(2690,3180) 2715.39,3154.61 C49.2@2715.39,3120 2712.6,3117.2 U11.3@2712.6,3037.24 ; v1(3000,1570) 3020,1590 3117.91,1590 C71.2@3120,1587.91 ; C71.2@3143.87,1590 3163.59,1570.28 3163.59,1550.46 3169.45,1544.61 C72.2@3220,1544.61 3223.39,1541.22 3305,1541.22 U20.16@3308.78,1545 ; v1(3400,11030) R73.2@3450.47,11030 ; v1(3400,11110) R72.2@3450.47,11110 ; v1(3400,11190) R74.2@3450.47,11190 ; U23.16@3648.39,11040 3648.39,10963.78 C86.2@3644.61,10960 3657.33,10947.27 3677.73,10947.27 v1(3700,10925) ; U24.8@3657.28,10745 3657.28,10807.32 C85.2@3654.61,10810 3660,10815.39 v1(3660,10870) ; v1(4125,6545) 4160,6510 U21.1@4160,6440
  Top Layer w15: R77E.2@1909.53,6375 v1(1980,6375)
  Top Layer w25: v1(1190,7460) v1(1260,7460) ; v1(1200,6940) v1(1260,6940) ; v1(1260,7000) v1(1260,6940) ; v1(1260,7520) v1(1260,7460) ; R43.2@1302.44,6940 v1(1260,6940) ; R47.2@1302.44,7460 v1(1260,7460)
  Top Layer w30: R31.1@2786.1,2830 v1(2860,2830) 2860,2757.5 v1(2852.5,2750)
  Bottom Layer w15: U1A.3@3456.93,3187.4 U1A.4@3573.07,3187.4 3578.37,3192.7 3613.09,3192.7 C90A.2@3650.39,3230 3650.2,3230.2 3650.2,3289.8 v1(3650,3290) ; U1C.3@3461.93,5137.4 U1C.4@3578.07,5137.4 3583.37,5142.7 3618.09,5142.7 C90C.2@3655.39,5180 3655.2,5180.2 3655.2,5239.8 v1(3655,5240) ; U1B.3@3476.93,7897.4 U1B.4@3593.07,7897.4 3598.37,7902.7 3633.09,7902.7 C90B.2@3670.39,7940 3670.2,7940.2 3670.2,7999.8 v1(3670,8000) ; U1D.3@3503.09,10003.4 U1D.4@3619.23,10003.4 3624.52,10008.7 3659.25,10008.7 C90D.2@3696.55,10046 3696.35,10046.2 3696.35,10105.8 v1(3696.16,10106) ; U2A.5@3573.07,2947.6 3576.87,2943.8 3646.59,2943.8 3650.2,2940.2 3650.2,2880.2 v1(3650,2880) ; U2C.5@3578.07,4897.6 3581.87,4893.8 3651.59,4893.8 3655.2,4890.2 3655.2,4830.2 v1(3655,4830) ; U2B.5@3593.07,7657.6 3596.87,7653.8 3666.59,7653.8 3670.2,7650.2 3670.2,7590.2 v1(3670,7590) ; U2D.5@3619.23,9763.6 3623.03,9759.8 3692.75,9759.8 3696.35,9756.2 3696.35,9696.2 v1(3696.16,9696)
pads on no net: D1A.2 D1B.2 D1C.2 D1D.2 D1E.2 D1F.2 DC1.2 DC2.2 DC3.2 DC4.2 DC5.3 J3.MT1 J3.MT2 J4.MT1 J4.MT2 J5.MT1 J5.MT2 J6.MT1 J6.MT2 J7.MT1 J7.MT2 J8.MT1 J8.MT2 J9.MT1 J9.MT2 J10.MT1 J10.MT2 J11.MT1 J11.MT2 J12.MT1 J12.MT2 J13.MT1 J13.MT2 J14.MT1 J14.MT2 J15.MT1 J15.MT2 J16.MT1 J16.MT2 J17.MT1 J17.MT2 J18.MT1 J18.MT2 MH1.1 MH2.1 MH4.1 MH5.1 MH7.1 MH8.1 MH9.1 MH10.1 MH11.1 U5.2 U5.3 U5.6 U7.2 U7.3 U7.6 U16.10 U17.10 U18.2 U18.6 U18.8 U18.10 U18.11 U18.15 U20.6

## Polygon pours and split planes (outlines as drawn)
NetFB2_2 on Top Layer "NONET_L06_P-001" (solid, pour order 16): 6510,555 6510,25 6975,25 6975,555
NetFB1_2 on Top Layer "NONET_L06_P-001" (solid, pour order 13): 6495,11980 6495,11428.83 6970,11428.83 6970,11980
L_24V on Top Layer "NONET_L06_P-001" (solid, pour order 5): 2920,5920 2770,5920 2770,5680 2890,5680 2920,5650 2920,2570 2960,2530 3340,2530 3410,2600 3410,2700 3320,2790 3150,2790 3110,2830 3110,4400 3180,4470 3350,4470 3410,4530 3410,4670 3350,4730 3160,4730 3100,4790 3100,5480 3100,5740
R_24V on Top Layer "NONET_L06_P-001" (solid, pour order 4): 2770,6210 2960,6210 2960,7110 3080,7230 3360,7230 3410,7280 3410,7430 3370,7470 3140,7470 3090,7520 3090,9120 3150,9180 3320,9180 3400,9260 3400,9330 3310,9420 3020,9420 2920,9320 2920,7330 2770,7180
NetQ1_2 on Top Layer "NONET_L06_P-001" (solid, pour order 3): 2290,6000 2290,6460 2320,6490 2740,6490 2760,6470 2760,6320 2760,5365 2745,5350 2370,5350 2355,5365 2355,5765 2290,5830
NetJ7_1 on Top Layer "NONET_L06_P-001" (solid, remove dead copper, pour order 0): 665,2930 920,2930 920,2790 780,2790 780,690 765,675 585,675 575,685 575,841.52 602.68,865 670,865 670,1335 635,1370 595,1370 580,1385 580,1520 600,1540 650,1540 670,1560 670,2030 590,2030 570,2050 570,2200 590,2220 650,2220 670,2240 670,2685 585,2685 575,2695 575,2840
CHASIS2 on Top Layer "NONET_L06_P-001" (solid, pour order 15): 6596.49,936.89 6596.49,571.89 6911.49,571.89 6911.49,936.89
CHASIS1 on Top Layer "NONET_L06_P-001" (solid, pour order 14): 6592.5,11418.83 6592.5,11053.83 6907.5,11053.83 6907.5,11418.83
SYS_24V on Top Layer "NONET_L06_P-001" (solid, pour order 1): 1300,2790 1340,2750 1440,2750 1440,2990 1340,2990 1280,2930 940,2930 940,2790
SYS_24V on Top Layer "NONET_L06_P-001" (solid, pour order 2): 1920,6070 2200,6070 2270,6000 2270,5830 2260,5820 2220,5780 1920,5780
N187_L on Top Layer "NONET_L06_P-001" (solid, pour order 11): 6560,4635 6235,4635 5350,5520 5170,5520 5105,5455 5105,5315 5155,5265 5385,5265 5495,5155 5495,5075 5525,5045 5625,5045 5675,4995 5675,4895 5675,4635 5500,4460 5500,3695 5370,3565 5170,3565 5115,3510 5115,3390 5165,3340 5400,3340 5470,3270 5470,3115 5515,3070 5615,3070 5665,3120 5665,4345 5810,4490 6560,4490
N187_R on Top Layer "NONET_L06_P-001" (solid, pour order 12): 6570,8945 6010,8945 5930,9025 5930,9642.53 5355,10217.53 5175,10217.53 5110,10152.53 5110,10012.53 5160,9962.53 5390,9962.53 5470,9882.53 5470,9760 5505,9725 5621.28,9725 5670,9682.53 5670,8800 5505,8635 5505,8392.53 5375,8262.53 5175,8262.53 5120,8207.53 5120,8087.53 5170,8037.53 5405,8037.53 5475,7967.53 5475,7812.53 5520,7767.53 5620,7767.53 5670,7817.53 5670,8557.53 5907.47,8795 6570,8795
no net on Top Overlay "NONET_L-01_P-001" (solid): 4740,1155 4740,1295 5450,1295 5450,1155
P187_R on Bottom Layer "NONET_L06_P-001" (solid, pour order 9): 6570,8955 6115,8955 6026.55,8866.55 6026.55,7791.55 5470,7235 5115,7235 5055,7295 5055,7415 5135,7495 5360,7495 5515,7650 5515,7710 5545,7740 5765,7740 5880,7855 5880,8400 5880,9070 5769.19,9179.81 5165,9179.81 5094.9,9249.9 5094.9,9360 5144.81,9409.91 5420,9409.91 5475.05,9464.95 5475.05,9644.95 5528.2,9698.1 5601.9,9698.1 6026.55,9273.45 6190,9110 6570,9110
P187_L on Bottom Layer "NONET_L06_P-001" (solid, pour order 10): 6560,4645 6150,4645 6021.55,4516.55 6021.55,3091.55 5465,2535 5110,2535 5050,2595 5050,2715 5130,2795 5355,2795 5465,2905 5465,2980 5510,3025 5745,3025 5875,3155 5875,3700 5875,4370 5764.19,4479.81 5160,4479.81 5089.9,4549.9 5089.9,4660 5139.81,4709.91 5415,4709.91 5470.05,4764.95 5470.05,4944.95 5523.2,4998.1 5596.9,4998.1 5795,4800 6560,4800
GNDA on Int3 (Sign) "NONET_L06_P-001" (solid, pour order 7): 50,50 4140,50 4140,11950 50,11950
CHASIS2 on Int3 (Sign) "NONET_L06_P-001" (solid, pour order 19): 7000,6495 4250,6495 4250,0 7000,0
CHASIS1 on Int3 (Sign) "NONET_L06_P-001" (solid, pour order 17): 4250,6515 4250,12000 7000,12000 7000,6515
GNDA on Int2 (Sign) "NONET_L06_P-001" (solid, pour order 6): 50,11950 4145,11950 4145,75 50,75
CHASIS2 on Int2 (Sign) "NONET_L06_P-001" (solid, pour order 21): 4250,6485 4250,0 7000,0 7000,6485
CHASIS1 on Int2 (Sign) "NONET_L06_P-001" (solid, pour order 20): 4250,12000 4250,6515 7000,6515 7000,12000 4250.92,12000 4250.56,12000.36
CHASIS1 on Int4 (PWR) (split plane): 6979.9,6510.1 4250.23,6510.1 4250.23,11979.9 6979.9,11979.9
ISO_5V on Int4 (PWR) (split plane): 1994.9,10262.11 1747.89,10015.1 982.11,10015.1 655.1,10342.11 655.1,10347.89 942.11,10634.9 1870,10634.9 1871.95,10635.29 1873.6,10636.4 1994.9,10757.69
CHASIS2 on Int4 (PWR) (split plane): 6979.9,20.1 4250.23,20.1 4250.23,6499.9 6979.9,6499.9
ISO_24V on Int4 (PWR) (split plane): 2934.9,10827.89 2934.9,9215.1 1862.11,9215.1 1845.1,9232.11 1845.1,9770 1844.71,9771.95 1843.6,9773.6 1723.6,9893.6 1721.95,9894.71 1720,9895.1 422.11,9895.1 395.1,9922.11 395.1,10087.89 645,10337.79 976.4,10006.4 978.05,10005.29 980,10004.9 1750,10004.9 1751.95,10005.29 1753.6,10006.4 2003.6,10256.4 2004.71,10258.05 2005.1,10260 2005.1,10767.89 2172.11,10934.9 2827.89,10934.9
SYS_24V on Int4 (PWR) (split plane): 1344.9,11620.1 580,11620.1 578.05,11619.71 576.4,11618.6 296.4,11338.6 295.29,11336.95 294.9,11335 294.9,8325 295.29,8323.05 296.4,8321.4 298.05,8320.29 300,8319.9 1474.9,8319.9 1474.9,7950 1475.29,7948.05 1476.4,7946.4 1478.05,7945.29 1480,7944.9 1727.69,7944.9 1726.4,7943.6 1725.29,7941.95 1724.9,7940 1724.9,6480 1724.9,6220 1725.29,6218.05 1726.4,6216.4 1876.4,6066.4 1878.05,6065.29 1880,6064.9 2197.89,6064.9 2264.9,5997.89 2264.9,5832.11 2217.89,5785.1 1880,5785.1 1878.05,5784.71 1876.4,5783.6 1726.4,5633.6 1725.29,5631.95 1724.9,5630 1724.9,5555 1724.9,5400 1724.9,5370 1724.9,5080 1724.9,2635.1 1305.1,2635.1 1305.1,8090 1304.71,8091.95 1303.6,8093.6 1301.95,8094.71 1300,8095.1 105.1,8095.1 105.1,11372.89 557.11,11824.9 1344.9,11824.9
VCCA on Int4 (PWR) (split plane): 4145,20.1 20.1,20.1 20.1,11979.9 4145,11979.9
CHASIS1 on Int1 (GND) (split plane): 6979.9,6510.1 4250.23,6510.1 4250.23,11979.9 6979.9,11979.9
CHASIS2 on Int1 (GND) (split plane): 6979.9,20.1 4250.23,20.1 4250.23,6499.9 6979.9,6499.9
ISO_GND on Int1 (GND) (split plane): 2934.9,10827.89 2934.9,9215.1 1862.11,9215.1 1845.1,9232.11 1845.1,9770 1844.71,9771.95 1843.6,9773.6 1723.6,9893.6 1721.95,9894.71 1720,9895.1 422.11,9895.1 395.1,9922.11 395.1,10087.89 942.11,10634.9 1870,10634.9 1871.95,10635.29 1873.6,10636.4 2172.11,10934.9 2827.89,10934.9
GNDA on Int1 (GND) (split plane): 4145,20.1 20.1,20.1 20.1,11979.9 4145,11979.9

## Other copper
Int1 (GND) (plane layer: these items are gaps in the copper):
  rectangle: 4145,0 4250.23,12000
  lines w10: 4250,6505 7000,6505 ; 4250.23,0 7000,0 ; 390,9920 390,10090 940,10640 1870,10640 2170,10940 2830,10940 2940,10830 2940,9210 1860,9210 1840,9230 1840,9770 1720,9890 420,9890 390,9920
Int4 (PWR) (plane layer: these items are gaps in the copper):
  rectangle: 4145,0 4250.23,12000
  lines w10: 885,10105 650,10340 650,10350 940,10640 1870,10640 2000,10770 ; 4250,6505 7000,6505 ; 6995,5 7000,10 ; 2000,10770 2170,10940 2830,10940 2940,10830 2940,9210 1860,9210 1840,9230 1840,9770 1720,9890 420,9890 390,9920 390,10090 645,10345 980,10010 1750,10010 2000,10260 2000,10770 ; 100,8090 100,11375 555,11830 1350,11830 1350,11615 580,11615 300,11335 300,8325 1480,8325 1480,7950 1740,7950 1730,7940 1730,6480 1730,6220 1880,6070 2200,6070 2270,6000 2270,5830 2220,5780 1880,5780 1730,5630 1730,5555 1730,5400 1730,5370 1730,5080 1730,2630 1300,2630 1300,8090 100,8090

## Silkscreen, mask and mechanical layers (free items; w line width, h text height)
Top Overlay:
  text "34" at 2366,11776 h40
  text "64" at 746,11676 h40
  text "2" at 4086,11676 h40
  text "63" at 746,11576 h40
  text "1" at 4096,11576 h40
  text "CHASSIS" at 6469,11546 h40 r90
  text "33" at 2366,11486 h40
  text "TEMPERATURE" at 56,11264 h40 r270
  text "I2C_SDA" at 3295.29,11233.2 h40 r45
  text "TEMPERATURE" at 706,11214 h40 r270
  text "I2C_SCL" at 2730.29,11173.2 h40 r45
  text "BAYCAT_3V3" at 2965.29,10608.2 h40 r45
  text "GND" at 3910,10508.49 h40 r45
  text "GND" at 4135,10503.49 h40 r45
  text "ISO_5V" at 1645.29,10418.2 h40 r45
  text "MVC RS232 24V" at 56,10314 h40 r270
  text "MVC RS232 24V" at 686,10224 h40 r270
  text "IS0_24V" at 1660.29,9978.2 h40 r45
  text "ISO_GND" at 895.29,9818.2 h40 r45
  text "SIC RS232" at 56,9474 h40 r270
  text "SIC RS232" at 696,9404 h40 r270
  text "P187_R" at 6115.29,8958.2 h40 r45
  text "WARNING" at 5825,8930 h80 r90
  text "HIGH VOLTAGE!" at 5955,8930 h80 r90
  text "375V RIGHT" at 5700,8925 h80 r90
  text "SPARE 5V" at 56,8769 h40 r270
  text "SPARE 5V" at 706,8669 h40 r270
  text "375V LEFT INPUT" at 6950.52,8661.29 h40 r90
  text "N187_R" at 5730.29,8603.2 h40 r45
  text "375V LEFT INPUT" at 6334,8581 h40 r90
  text "PPS DISTRIBUTION" at 56,7729 h40 r270
  text "SYS_24V" at 1405.29,7593.2 h40 r45
  text "PPS DISTRO" at 696,7534 h40 r270
  text "5V" at 1354,7516 h40 r90
  text "24V" at 1494,7501 h40 r90
  text "SPARE SWITCHED" at 56,6999 h40 r270
  text "5V" at 1354,6986 h40 r90
  text "24V" at 1459,6971 h40 r90
  text "GND" at 2540,6943.49 h40 r45
  text "GND" at 2305,6938.49 h40 r45
  text "SPARE SWITCHED" at 696,6879 h40 r270
  text "WARNING!" at 4750,6710 h150
  text "R_24V" at 2910.29,6573.2 h40 r45
  text "HIGH VOLTAGE!" at 4750,6435 h150
  text "OR BYPASS" at 2906,6406 h40
  text "CISCO2_EN" at 2030.29,6298.2 h40 r45
  text "CISCO SW 2" at 56,6194 h40 r270
  text "WARNING!" at 4748.85,6154.08 h150
  text "CISCO SW 2" at 696,6134 h40 r270
  text "OR BYPASS" at 2896,5846 h40
  text "CISCO2_EN" at 1805.29,5648.2 h40 r45
  text "CISCO SW 1" at 56,5479 h40 r270
  text "CISCO SW 1" at 694.9,5428.11 h40 r270
  text "SYNCBOX_EN" at 1975.29,4878.2 h40 r45
  text "SYNC BOX" at 56,4749 h40 r270
  text "N187_R" at 5870.29,4748.2 h40 r45
  text "SYNC BOX" at 696,4669 h40 r270
  text "P187_R" at 5590.29,4523.2 h40 r45
  text "375V RIGHT INPUT" at 6964,4321 h40 r90
  text "375V RIGHT INPUT" at 6330.98,4283.95 h40 r90
  text "WARNING" at 6000,3985 h80 r90
  text "375V RIGHT" at 5875,3975 h80 r90
  text "HIGH VOLTAGE!" at 6170,3900 h80 r90
  text "L_24V" at 3055.29,3873.2 h40 r45
  text "MEDIA CONVERTER" at 56,3824 h40 r270
  text "MEDIA_EN" at 2035.29,3708.2 h40 r45
  text "MEDIA" at 696,3594 h40 r270
  text "SIC" at 66,2884 h40 r270
  text "SIC" at 679.87,2677.46 h40 r270
  text "UNSW 24V SPARE" at 56,2384 h40 r270
  text "24V SPARE" at 703.41,2246.71 h40 r270
  text "HOTEL POWER BOARD" at 4570,1695 h60
  text "FAULT" at 3920,1673.49 h40 r45
  text "UNSW 24V SPARE" at 56,1664 h40 r270
  text "9/26/2023   V1.0" at 4570,1575 h60
  text "SYS_5V" at 1465.29,1553.2 h40 r45
  text "24V SPARE" at 703.41,1527.97 h40 r270
  text "APL MARS" at 4568.54,1449.6 h60
  text "K. ZACK" at 4570,1335 h60
  text "GND" at 1110,1268.49 h40 r45
  text "SN:" at 4563.19,1207.59 h60
  text "UNSW 24V SPARE" at 56,974 h40 r270
  text "GND" at 1125,963.49 h40 r45
  text "24V SPARE" at 703.41,837.97 h40 r270
  text "34" at 2366,476 h40
  text "64" at 746,376 h40
  text "2" at 4086,376 h40
  text "63" at 746,276 h40
  text "1" at 4096,276 h40
  text "CHASSIS" at 6319,206 h40 r90
  text "33" at 2366,186 h40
